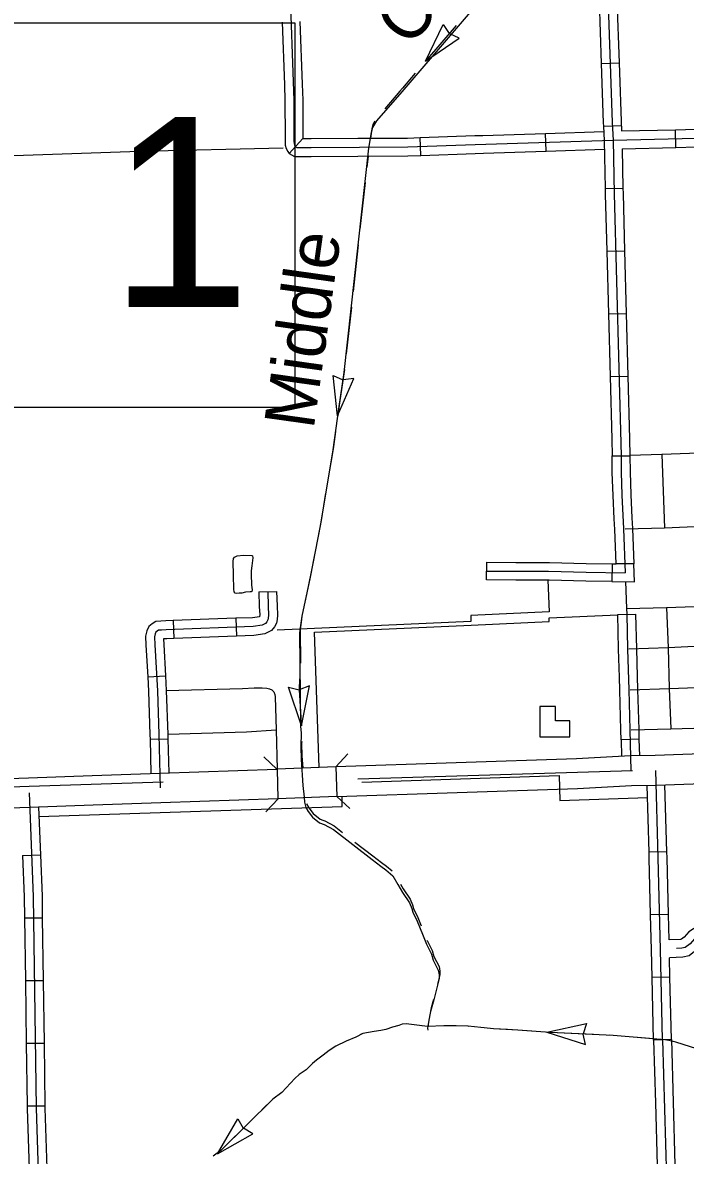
# Model space of a CAD drawing. Extents: x 1164457 to 1439835, y 1590918 to 1773502.
# Drawn here: x 1287953 to 1293538, y 1631604 to 1641151 of the extents above; entities that cross this region are included whole.
import ezdxf

# ---------------------------------------------------------------- set-up
doc = ezdxf.new("R2010")
doc.units = 0
for name, color, linetype in [('Level 15', 7, 'Continuous'), ('Level 31', 7, 'Continuous'), ('Level 32', 7, 'Continuous'), ('Level 33', 7, 'Continuous'), ('Level 34', 7, 'Continuous'), ('Level 35', 7, 'Continuous'), ('Level 37', 7, 'Continuous'), ('Level 43', 7, 'Continuous'), ('Level 45', 7, 'Continuous'), ('Level 5', 7, 'Continuous'), ('Level 58', 7, 'Continuous'), ('Level 6', 7, 'Continuous'), ('R_Draft', 7, 'Continuous')]:
    doc.layers.add(name, color=color, linetype=linetype)

msp = doc.modelspace()

# ---------------------------------------------------------------- linework, layer by layer
at = {"layer": 'Level 15'}
for points in [[(1294870.3, 1634777.6), (1294862.8, 1635027.5), (1294743.4, 1635023.9), (1294410.1, 1635010.5), (1294147.1, 1635001.7), (1293830.1, 1634993.2), (1293285.2, 1634972.7), (1293076, 1634969.7), (1292619.8, 1634946.4), (1290592.7, 1634878.6)], [(1287756.1, 1634777.3), (1288003.4, 1634785.6), (1288539.1, 1634805.7), (1289108.2, 1634825), (1290095.9, 1634859.3), (1290097.5, 1634859.4), (1290104.5, 1634609.5)], [(1290592.7, 1634878.6), (1290097.5, 1634859.4)], [(1290592.7, 1634878.6), (1290601, 1634628.8), (1292630.4, 1634696.6), (1293084.1, 1634719.8), (1293291.7, 1634722.8), (1293838.2, 1634743.4), (1294154.6, 1634751.8), (1294419.3, 1634760.7), (1294752.1, 1634774.1), (1294870.3, 1634777.6)], [(1290601, 1634628.8), (1290104.5, 1634609.5)], [(1290104.5, 1634609.5), (1289116.8, 1634575.2), (1288548, 1634555.9), (1288012.3, 1634535.7), (1287764.5, 1634527.4)]]:
    msp.add_lwpolyline(points, dxfattribs=at)
at = {"layer": 'Level 31'}
for p, q in [((1292921.8, 1637500.3), (1293071.8, 1637500.9)), ((1291863.4, 1636453.2), (1291864.6, 1636603.2)), ((1291864.6, 1636603.2), (1291864.6, 1636603.2)), ((1292920.8, 1636590.7), (1292919, 1636440.7)), ((1292969.8, 1636162.5), (1293119.7, 1636165.5)), ((1293147.6, 1635110.5), (1292997.6, 1635106.3)), ((1292997.6, 1635106.3), (1292997.6, 1635106.3))]:
    msp.add_line(p, q, dxfattribs=at)
for points in [[(1292938.9, 1636969.4), (1292929.6, 1637164.4), (1292922.4, 1637360.3), (1292921.8, 1637500.3)], [(1292996.8, 1637500.6), (1292997.4, 1637361.9), (1293004.5, 1637167.6), (1293018.1, 1636883.2), (1293032.2, 1636514.4)], [(1293071.8, 1637500.9), (1293072.4, 1637363.4), (1293079.4, 1637170.8), (1293088.7, 1636976.6)], [(1293104.4, 1636588.6), (1292954.2, 1636590.3), (1292943.2, 1636880), (1292938.9, 1636969.4)], [(1293088.7, 1636976.6), (1293093.1, 1636886.4), (1293104.4, 1636588.6)], [(1291864, 1636528.2), (1292109.3, 1636526.3), (1292386.3, 1636526.3), (1292701.3, 1636518.3), (1293032.2, 1636514.4)], [(1291864.6, 1636603.2), (1292109.6, 1636601.3), (1292387.2, 1636601.3), (1292393.9, 1636601.1)], [(1292393.9, 1636601.1), (1292702.7, 1636593.3), (1292920.8, 1636590.7)], [(1292919, 1636440.7), (1293110.1, 1636438.5), (1293104.4, 1636588.6)], [(1292920.8, 1636590.7), (1292954.2, 1636590.3)], [(1292390.1, 1636451.1), (1292385.3, 1636451.3), (1292109, 1636451.3), (1291863.4, 1636453.2)], [(1292919, 1636440.7), (1292699.9, 1636443.3), (1292390.1, 1636451.1)], [(1292982.9, 1635633.8), (1292975.6, 1635868.8), (1292969.8, 1636162.5)], [(1293044.7, 1636164), (1293050.6, 1635870.7), (1293061.3, 1635526.7), (1293070.3, 1635190.7), (1293080, 1634844.7)], [(1293119.7, 1636165.5), (1293125.6, 1635872.6), (1293132.9, 1635638.5)], [(1292997.6, 1635106.3), (1292995.3, 1635188.6), (1292986.3, 1635524.5), (1292982.9, 1635633.8)], [(1293132.9, 1635638.5), (1293136.3, 1635528.9), (1293145.3, 1635192.8), (1293147.6, 1635110.5)], [(1292997.6, 1635106.3), (1293001.6, 1634965.9)], [(1293147.6, 1635110.5), (1293151.5, 1634970.8)]]:
    msp.add_lwpolyline(points, dxfattribs=at)
at = {"layer": 'Level 32'}
for p, q in [((1292829.7, 1640806), (1292979.6, 1640811.1)), ((1292848.2, 1640276.9), (1292998, 1640284.7)), ((1293459, 1640098.8), (1293455.4, 1640248.7)), ((1292862.4, 1639751.6), (1293012.4, 1639754.6)), ((1292876.1, 1639223.3), (1293026.1, 1639227.2)), ((1292890.1, 1638695.5), (1293040, 1638699.4)), ((1292904.1, 1638167.7), (1293054, 1638171.6)), ((1289944.1, 1636352.4), (1290094.1, 1636356.7)), ((1289221.6, 1636110.5), (1289227.2, 1635960.6)), ((1289749.2, 1636130.3), (1289754.8, 1635980.4)), ((1289007.6, 1635636.9), (1289157.4, 1635645.3)), ((1289026.8, 1635111.6), (1289176.7, 1635115.5)), ((1293383.4, 1634163.1), (1293233.5, 1634158.7)), ((1287953.4, 1634130.1), (1288103.2, 1634136)), ((1287969.2, 1633604.3), (1288119.2, 1633606.3)), ((1293396.1, 1633634.8), (1293246.2, 1633631.3)), ((1293408.5, 1633106.9), (1293258.6, 1633103.4)), ((1287976.4, 1633076.4), (1288126.4, 1633078.4)), ((1287983.6, 1632548.4), (1288133.6, 1632550.4)), ((1293420.9, 1632579.1), (1293271, 1632575.6)), ((1287990.8, 1632020.5), (1288140.8, 1632022.5))]:
    msp.add_line(p, q, dxfattribs=at)
for points in [[(1292595.2, 1650835.6), (1292619.2, 1650245.4), (1292635.6, 1649303.5), (1292664.5, 1648188.9), (1292730.3, 1645988.2), (1292748.5, 1645496.5), (1292786.1, 1644344.5), (1292832.7, 1642827.7), (1292882.3, 1641465.2), (1292921.6, 1640309.2), (1292929.3, 1640161.1)], [(1292811.7, 1641333.7), (1292829.7, 1640806)], [(1292961.7, 1641338.8), (1292979.6, 1640811.1)], [(1292829.7, 1640806), (1292846.6, 1640306), (1292848.2, 1640276.9)], [(1292979.6, 1640811.1), (1292999.1, 1640237.8)], [(1292929.3, 1640161.1), (1293627.3, 1640177.8), (1294901.9, 1640225.9), (1295551.7, 1640247.8), (1297052.5, 1640298.3), (1297477.1, 1640311), (1298072.3, 1640333.4), (1298167.4, 1640347), (1298194.4, 1640359), (1298210.9, 1640377), (1298228.9, 1640389), (1298248.4, 1640392)], [(1292848.2, 1640276.9), (1292854.3, 1640158.4), (1292862.4, 1639751.6)], [(1292999.1, 1640237.8), (1293455.4, 1640248.7)], [(1293455.4, 1640248.7), (1293625, 1640252.8), (1293982, 1640266.3)], [(1292929.3, 1640161.1), (1292938.3, 1639707.6), (1292996.8, 1637500.6)], [(1293005.8, 1640087.9), (1293459, 1640098.8)], [(1293005.8, 1640087.9), (1293012.4, 1639754.6)], [(1293459, 1640098.8), (1293629.6, 1640102.9), (1293987.7, 1640116.4)], [(1292862.4, 1639751.6), (1292863.3, 1639705.9), (1292876.1, 1639223.3)], [(1293012.4, 1639754.6), (1293013.3, 1639709.4), (1293026.1, 1639227.2)], [(1292876.1, 1639223.3), (1292890.1, 1638695.5)], [(1293026.1, 1639227.2), (1293040, 1638699.4)], [(1292890.1, 1638695.5), (1292904.1, 1638167.7)], [(1293040, 1638699.4), (1293054, 1638171.6)], [(1292904.1, 1638167.7), (1292918, 1637639.8)], [(1293054, 1638171.6), (1293068, 1637643.8)], [(1292918, 1637639.8), (1292921.8, 1637500.3)], [(1293068, 1637643.8), (1293071.8, 1637500.9)], [(1290019.1, 1636354.5), (1290022.6, 1636232.5), (1290026.2, 1636157.8), (1290023.9, 1636132.6), (1290020.3, 1636116.4), (1290011.9, 1636100.2), (1290001.4, 1636086.8), (1289971.7, 1636071.4), (1289896, 1636060.8), (1289164.1, 1636033.3), (1289122.7, 1636030.9), (1289098.7, 1636029.2), (1289087.2, 1636022.7), (1289077.1, 1636014.4), (1289070.6, 1636000.1), (1289064.4, 1635973.5), (1289067.6, 1635906.6), (1289089.3, 1635519.8), (1289100.8, 1635149.8), (1289112.5, 1634700.1)], [(1289944.1, 1636352.4), (1289947.7, 1636229.6), (1289951, 1636159.4), (1289949.7, 1636144.5), (1289948.6, 1636143.9), (1289889.3, 1636135.6), (1289749.2, 1636130.3)], [(1290094.1, 1636356.7), (1290097.6, 1636235.3), (1290101.3, 1636156.2), (1290098.2, 1636121.1), (1290091.4, 1636090.6), (1290075.2, 1636059.4), (1290050.3, 1636027.7), (1289994.9, 1635998.9), (1289902.6, 1635986), (1289754.8, 1635980.4)], [(1289221.6, 1636110.5), (1289160.6, 1636108.2), (1289117.8, 1636105.8), (1289076.5, 1636102.7), (1289044.6, 1636084.7), (1289016.1, 1636061.3), (1288999.3, 1636024.5), (1288989, 1635980.3), (1288992.7, 1635902.7), (1289007.6, 1635636.9)], [(1289749.2, 1636130.3), (1289221.6, 1636110.5)], [(1289227.2, 1635960.6), (1289167.7, 1635958.4), (1289140.3, 1635956.8), (1289142.5, 1635910.5), (1289157.4, 1635645.3)], [(1289754.8, 1635980.4), (1289227.2, 1635960.6)], [(1289007.6, 1635636.9), (1289014.3, 1635516.5), (1289025.8, 1635147.7), (1289026.8, 1635111.6)], [(1289157.4, 1635645.3), (1289164.2, 1635523.1), (1289175.8, 1635152), (1289176.7, 1635115.5)], [(1289026.8, 1635111.6), (1289034.3, 1634822.5)], [(1289176.7, 1635115.5), (1289184.2, 1634827.6)], [(1293345.9, 1632577.3), (1293328, 1633338.7), (1293309.9, 1634110.7), (1293288.5, 1634847.7)], [(1293233.5, 1634158.7), (1293217.1, 1634721.7)], [(1293383.4, 1634163.1), (1293367, 1634725.6)], [(1288007.8, 1634660.6), (1288041.8, 1633785.8), (1288066.1, 1632000.6), (1288103.1, 1630845.4)], [(1288087.6, 1634538.6), (1288103.2, 1634136)], [(1293246.2, 1633631.3), (1293234.9, 1634108.7), (1293233.5, 1634158.7)], [(1293396.1, 1633634.8), (1293384.9, 1634112.7), (1293383.4, 1634163.1)], [(1287953.4, 1634130.1), (1287966.8, 1633783.9), (1287969.2, 1633604.3)], [(1288103.2, 1634136), (1288116.8, 1633787.8), (1288119.2, 1633606.3)], [(1294219.2, 1633888.6), (1294219.6, 1633848.5), (1294217.5, 1633803.8), (1294200.4, 1633746.2), (1294172.7, 1633671.6), (1294138.6, 1633584.1), (1294110.9, 1633543.6), (1294083.2, 1633511.6), (1294057.6, 1633496.7), (1294023.5, 1633490.3), (1293808.2, 1633492.4), (1293752.8, 1633488.2), (1293720.8, 1633481.8), (1293678.2, 1633469), (1293616.3, 1633428.5), (1293578, 1633387.9), (1293537.5, 1633356), (1293507.6, 1633349.6), (1293465, 1633347.4)], [(1287969.2, 1633604.3), (1287976.4, 1633076.4)], [(1288119.2, 1633606.3), (1288126.4, 1633078.4)], [(1293258.6, 1633103.4), (1293253.1, 1633337), (1293246.2, 1633631.3)], [(1293401.2, 1633419.3), (1293396.1, 1633634.8)], [(1293917.1, 1633566.4), (1293805.7, 1633567.5), (1293742.5, 1633562.6), (1293702.6, 1633554.6), (1293646.2, 1633537.7), (1293567.9, 1633486.4), (1293527.2, 1633443.4), (1293504.7, 1633425.6), (1293497.8, 1633424.2), (1293401.2, 1633419.3)], [(1293915.6, 1633416.4), (1293810.7, 1633417.4), (1293763, 1633413.7), (1293739, 1633408.9), (1293710.2, 1633400.3), (1293664.8, 1633370.5), (1293628.7, 1633332.4), (1293570.3, 1633286.3), (1293517.4, 1633275), (1293404.7, 1633269.3)], [(1293408.5, 1633106.9), (1293404.7, 1633269.3)], [(1293271, 1632575.2), (1293258.6, 1633103.4)], [(1293420.9, 1632579.5), (1293408.5, 1633106.9)], [(1287976.4, 1633076.4), (1287983.6, 1632548.4)], [(1288126.4, 1633078.4), (1288133.6, 1632550.4)], [(1287983.6, 1632548.4), (1287990.8, 1632020.5)], [(1288133.6, 1632550.4), (1288140.8, 1632022.5)], [(1287990.8, 1632020.5), (1287991.1, 1631998.9), (1288007.3, 1631491.3)], [(1288140.8, 1632022.5), (1288141, 1632002.3), (1288157.3, 1631496.1)]]:
    msp.add_lwpolyline(points, dxfattribs=at)
at = {"layer": 'Level 33'}
for points in [[(1293339.9, 1637512), (1293363.7, 1636894.1)], [(1293032.5, 1636883.6), (1293363.7, 1636894.1), (1293744.9, 1636909.2), (1293984.9, 1636923.4), (1294334.7, 1636935.3)], [(1293035, 1636439.4), (1293043.7, 1636211.9), (1293044.7, 1636164)], [(1293043.7, 1636211.9), (1293378.6, 1636221.7), (1293770.5, 1636236.2), (1294359.8, 1636251.3)], [(1293378.6, 1636221.7), (1293393.2, 1635882.7), (1293402.6, 1635539.2), (1293415.2, 1635198.2)], [(1294371.8, 1635912.7), (1293933.8, 1635901.1), (1293781.6, 1635902.2), (1293393.2, 1635882.7), (1293062.1, 1635871.1)], [(1293402.6, 1635539.2), (1293790, 1635553.7), (1294385.3, 1635577.4)], [(1293081.9, 1635191), (1293415.2, 1635198.2), (1293705.5, 1635207.1), (1293814.4, 1635211.7), (1293829.4, 1635211.7)]]:
    msp.add_lwpolyline(points, dxfattribs=at)
at = {"layer": 'Level 34'}
for points in [[(1295681.5, 1637580.2), (1295410.1, 1637568.9), (1294654.4, 1637551), (1294315, 1637541.9), (1293960.9, 1637532.7), (1293339.9, 1637512), (1293071.7, 1637503.1)], [(1289164.2, 1635522.3), (1289805.4, 1635539.8), (1289903.7, 1635543.4), (1289972, 1635544.1), (1290011.4, 1635541), (1290033.6, 1635535.2), (1290052.6, 1635526.4), (1290069.1, 1635511), (1290078, 1635489), (1290081.3, 1635468.8), (1290089.6, 1635190.4), (1290097.5, 1634859.4)], [(1293072.1, 1635527.1), (1293402.6, 1635539.2)], [(1289175.7, 1635154.1), (1289840.9, 1635173.9), (1290089.6, 1635190.4)]]:
    msp.add_lwpolyline(points, dxfattribs=at)
at = {"layer": 'Level 35'}
for points in [[(1289729.6, 1636493.1), (1289728.4, 1636608), (1289729.6, 1636634.1), (1289737.9, 1636645.9), (1289761.6, 1636655.4), (1289813.7, 1636661.3), (1289883.5, 1636660.2), (1289890.6, 1636656.6), (1289893, 1636640), (1289883.5, 1636571.3), (1289878.8, 1636531), (1289880, 1636501.4)], [(1289880, 1636501.4), (1289882.3, 1636409), (1289887.1, 1636368.8), (1289885.9, 1636356.9), (1289880, 1636353.4), (1289870.5, 1636352.2), (1289832.6, 1636351), (1289799.5, 1636342.7), (1289778.1, 1636341.5), (1289759.2, 1636340.3), (1289743.8, 1636342.7), (1289736.7, 1636352.2), (1289734.3, 1636377), (1289729.6, 1636493.1)]]:
    msp.add_lwpolyline(points, dxfattribs=at)
at = {"layer": 'Level 37'}
for points in [[(1289986.6, 1634961.5), (1290096.5, 1634859.4)], [(1290592.3, 1634878.6), (1290694.4, 1634988.5)], [(1290711.3, 1634526.6), (1290601.4, 1634628.8)], [(1290105.6, 1634609.5), (1290003.4, 1634499.7)]]:
    msp.add_lwpolyline(points, dxfattribs=at)
at = {"layer": 'Level 43'}
for p, q in [((1291348.3, 1640824.9), (1291496.5, 1641134.5)), ((1291496.5, 1641134.5), (1291548.1, 1641059.1)), ((1291348.3, 1640824.9), (1291631.4, 1641018.9)), ((1291631.4, 1641018.9), (1291549, 1641058.3)), ((1290607.9, 1637836.1), (1290569, 1638177.1)), ((1290569, 1638177.1), (1290652.8, 1638140.7)), ((1290607.9, 1637836.1), (1290744.7, 1638150.9)), ((1290744.7, 1638150.9), (1290654, 1638140.5)), ((1290194, 1635549.5), (1290282.7, 1635527.8)), ((1290304, 1635224.5), (1290194, 1635549.5)), ((1290371.2, 1635561), (1290282.7, 1635527.8)), ((1290304, 1635224.5), (1290371.2, 1635561)), ((1292369.8, 1632641.6), (1292705.2, 1632714.2)), ((1292705.2, 1632714.2), (1292677.4, 1632627.2)), ((1292369.8, 1632641.6), (1292696.6, 1632536.8)), ((1292696.6, 1632536.8), (1292677.3, 1632626)), ((1289594.3, 1631615.9), (1289768.1, 1631911.9)), ((1289768.1, 1631911.9), (1289813.2, 1631832.4)), ((1289594.3, 1631615.9), (1289892.8, 1631785.3)), ((1289892.8, 1631785.3), (1289814.1, 1631831.5))]:
    msp.add_line(p, q, dxfattribs=at)
for points in [[(1292471.3, 1642111.9), (1291148, 1640567.2), (1290936.9, 1640321.8), (1290919.2, 1640294.8), (1290902.7, 1640267), (1290891.3, 1640224.3), (1290869.2, 1640093.5), (1290661.4, 1638202), (1290618.8, 1637916.7), (1290567.4, 1637548.9), (1290463.1, 1636924.1), (1290376.4, 1636478.2), (1290306.5, 1636147.6), (1290294.7, 1636068.3), (1290285.8, 1636006.7), (1290296.2, 1635219.6), (1290300.8, 1635163.6), (1290299.1, 1635048.6), (1290301.4, 1634939.6), (1290315.5, 1634721.8), (1290325, 1634622.3), (1290328.1, 1634581.8), (1290340.8, 1634535.3), (1290359.7, 1634502.1), (1290395.6, 1634455.1), (1290456, 1634407.7), (1290495, 1634392.3), (1290572.6, 1634349.3), (1290899.3, 1634096.3), (1290971.5, 1634042.5), (1291015.3, 1634010.5), (1291074.2, 1633959), (1291115.4, 1633887), (1291154, 1633820.1), (1291213.6, 1633732.7), (1291233.3, 1633683.6), (1291241.6, 1633654.8), (1291277, 1633578.3), (1291324.2, 1633467.7), (1291355.9, 1633383.6), (1291398.8, 1633298.7), (1291412.9, 1633249), (1291456.6, 1633164.9), (1291463.7, 1633125.5), (1291464.9, 1633093.5), (1291437.8, 1632994.4), (1291418.1, 1632914.4), (1291389.8, 1632815.8), (1291375.2, 1632742.9), (1291364.9, 1632677), (1291367.3, 1632659.3)], [(1291605.9, 1641125.7), (1291348.3, 1640824.9)], [(1291262.4, 1640724.7), (1291153.7, 1640597.8), (1291133.5, 1640574.4)], [(1291133.5, 1640574.4), (1291004.4, 1640424.2)], [(1290922.3, 1640321.2), (1290908.4, 1640297.6), (1290896.9, 1640254.9), (1290883.7, 1640176.6)], [(1290864.1, 1640026.4), (1290853.9, 1639933.5)], [(1290839.5, 1639802.3), (1290796.2, 1639408.7)], [(1290781.8, 1639277.5), (1290738.6, 1638883.8)], [(1290724.2, 1638752.6), (1290680.9, 1638359)], [(1290666.3, 1638227.8), (1290624.5, 1637947.3), (1290608.9, 1637836)], [(1290590.7, 1637705.2), (1290573.1, 1637579.5), (1290561.4, 1637509.4)], [(1290561.4, 1637509.4), (1290528.8, 1637314.1)], [(1290507, 1637184), (1290468.7, 1636954.6), (1290437.5, 1636794.1)], [(1290412.3, 1636664.6), (1290382.1, 1636508.7), (1290333, 1636276.6)], [(1290307.6, 1636147.1), (1290300.4, 1636098.9), (1290291.5, 1636037.3), (1290295.2, 1635752.3)], [(1290286.9, 1635620.6), (1290282.7, 1635527.8), (1290301.8, 1635250.2), (1290304, 1635224.5)], [(1290304.9, 1635092.6), (1290304.7, 1635079.1), (1290307.1, 1634970.2), (1290313.7, 1634867.8)], [(1290346, 1634567.3), (1290346.4, 1634565.9), (1290365.4, 1634532.7), (1290401.2, 1634485.6), (1290461.6, 1634438.3), (1290482.5, 1634430)], [(1290482.5, 1634430), (1290500.7, 1634422.9), (1290578.3, 1634379.9), (1290649.2, 1634324.9)], [(1290753.6, 1634244.1), (1290905, 1634126.9), (1290977.1, 1634073.1), (1291020.9, 1634041.1), (1291066.3, 1634001.5)], [(1291136.6, 1633890.7), (1291159.6, 1633850.7), (1291219.2, 1633763.3), (1291239, 1633714.2), (1291247.3, 1633685.3), (1291282.7, 1633608.9), (1291312.8, 1633538.2)], [(1291361.1, 1633415.4), (1291361.6, 1633414.2), (1291404.4, 1633329.3), (1291418.6, 1633279.5), (1291462.3, 1633195.5), (1291469.4, 1633156.1), (1291470.6, 1633124.1), (1291449.2, 1633045.9)], [(1291416, 1632918.1), (1291395.4, 1632846.4), (1291380.9, 1632773.5), (1291370.6, 1632707.6), (1291373, 1632689.9)], [(1293697.1, 1632481), (1293458.8, 1632558.5), (1293398.9, 1632571.6), (1293364.6, 1632577.9), (1292930, 1632614.4), (1292400, 1632640.1), (1292127.9, 1632659.1), (1291921.1, 1632670.1), (1291707.8, 1632691.2), (1291607.5, 1632695.4), (1291504.3, 1632695), (1291366.3, 1632689.6), (1291186.2, 1632711), (1291151.4, 1632709.2), (1291122.8, 1632699.1), (1291071.4, 1632684.6), (1291014, 1632665.4), (1290971.4, 1632654.7), (1290916.9, 1632646.4), (1290819.8, 1632631), (1290760.6, 1632599.9), (1290681.1, 1632566), (1290592.1, 1632523.5), (1290537.8, 1632486.7), (1290485.6, 1632447.1), (1290430.5, 1632405.2), (1290395.8, 1632377.4), (1290343.2, 1632325.7), (1290283.1, 1632284.5), (1290248.1, 1632252.8), (1290138.1, 1632132.7), (1290063, 1632077.7), (1289622.9, 1631644.1), (1289557.9, 1631597.4)], [(1291185.3, 1632711), (1291151.4, 1632709.2), (1291122.8, 1632699.1), (1291071.4, 1632684.6), (1291014, 1632665.4), (1290971.4, 1632654.7), (1290916.9, 1632646.4), (1290819.8, 1632631), (1290801.7, 1632621.5)], [(1291711.8, 1632690.8), (1291707.8, 1632691.2), (1291607.5, 1632695.4), (1291504.3, 1632695), (1291366.3, 1632689.6), (1291316.3, 1632695.5)], [(1292040.6, 1632663.7), (1291921.1, 1632670.1), (1291843.1, 1632677.8)], [(1292238.2, 1632651.4), (1292127.9, 1632659.1), (1292040.6, 1632663.7)], [(1292765.4, 1632622.4), (1292400, 1632640.1), (1292369.9, 1632642.2)], [(1293270.7, 1632585.8), (1292930, 1632614.4), (1292897.2, 1632616)], [(1290681.9, 1632566.3), (1290681.1, 1632566), (1290592.1, 1632523.5), (1290537.8, 1632486.7), (1290485.6, 1632447.1), (1290430.5, 1632405.2), (1290395.8, 1632377.4), (1290358.9, 1632341.1)], [(1293799, 1632444.4), (1293697.1, 1632481), (1293458.8, 1632558.5), (1293422.5, 1632566.4)], [(1290255.6, 1632259.6), (1290248.1, 1632252.8), (1290138.1, 1632132.7), (1290063, 1632077.7), (1289970.4, 1631986.5)], [(1289876.4, 1631893.8), (1289622.9, 1631644.1), (1289590.3, 1631620.7)]]:
    msp.add_lwpolyline(points, dxfattribs=at)
at = {"layer": 'Level 45'}
for p, q in [((1290198.9, 1640046.8), (1290314.7, 1640172.9)), ((1291309.2, 1640032.2), (1291303.8, 1640182.1)), ((1292364.3, 1640067.8), (1292359.5, 1640217.8))]:
    msp.add_line(p, q, dxfattribs=at)
for points in [[(1292803.2, 1642801.9), (1290299.1, 1642808.5), (1290275.8, 1642804.1), (1290255, 1642795.7), (1290243.4, 1642787.9), (1290218.1, 1642768.9), (1290198.3, 1642747.4), (1290182.2, 1642725.7), (1290172.5, 1642696.8), (1290166.1, 1642652.6), (1290165.1, 1642553.1), (1290238.8, 1640495.6), (1290239.7, 1640188), (1290239.7, 1640151.2), (1290240.6, 1640130), (1290243.3, 1640119.2), (1290252.5, 1640103.5), (1290263.6, 1640097.8), (1290281.9, 1640097.9), (1290308.7, 1640097.8), (1290385.1, 1640098.7), (1291198.8, 1640103.3), (1291765.8, 1640123.6), (1292929.3, 1640161.1)], [(1290140.2, 1641154.1), (1290159, 1640626.4)], [(1290290.1, 1641159.5), (1290308.9, 1640631.8)], [(1290308.9, 1640631.8), (1290313.8, 1640497), (1290314.7, 1640172.9)], [(1290159, 1640626.4), (1290163.8, 1640494.1), (1290164.7, 1640187.9), (1290164.7, 1640149.6), (1290166, 1640119.2), (1290173.2, 1640090.5), (1290187.6, 1640066)], [(1290314.7, 1640172.9), (1290384.5, 1640173.7), (1290778.2, 1640176)], [(1290778.2, 1640176), (1291197.2, 1640178.3), (1291303.8, 1640182.1)], [(1291303.8, 1640182.1), (1291763.2, 1640198.6), (1291831.8, 1640200.8)], [(1291831.8, 1640200.8), (1292359.5, 1640217.8)], [(1292359.5, 1640217.8), (1292850.4, 1640233.6)], [(1290187.6, 1640065.9), (1290198.9, 1640046.8), (1290245.6, 1640022.8), (1290281.9, 1640022.9), (1290309.1, 1640022.8), (1290385.8, 1640023.7), (1290779, 1640026)], [(1291836.6, 1640050.8), (1292364.3, 1640067.8)], [(1292364.3, 1640067.8), (1292855.8, 1640083.7)], [(1290779, 1640026), (1291200.3, 1640028.3), (1291309.2, 1640032.2)], [(1291309.2, 1640032.2), (1291768.3, 1640048.6), (1291836.6, 1640050.8)], [(1293271, 1632575.6), (1293286, 1632047.4)], [(1293345.9, 1632577.3), (1293395.8, 1630824.2)], [(1293420.9, 1632579.1), (1293435.9, 1632051.7)], [(1293286, 1632047.4), (1293301, 1631519.6)], [(1293435.9, 1632051.7), (1293450.9, 1631523.9)]]:
    msp.add_lwpolyline(points, dxfattribs=at)
at = {"layer": 'Level 5'}
msp.add_lwpolyline([(1287712.4, 1640026.5), (1288939.5, 1640067.5), (1290150.1, 1640095.7)], dxfattribs=at)
at = {"layer": 'Level 58'}
msp.add_lwpolyline([(1292311.1, 1635132.2), (1292565.1, 1635132.2), (1292565.1, 1635266.2), (1292444.9, 1635266.2), (1292444.9, 1635386.2), (1292311.1, 1635386.2)], close=True, dxfattribs=at)
at = {"layer": 'Level 6'}
for points in [[(1292380.3, 1636451.3), (1292389.4, 1636184), (1291730, 1636153.8), (1291731.7, 1636103.8), (1290413, 1636043.4), (1290098.1, 1636028.9)], [(1290452.9, 1634873.2), (1290414.4, 1636013.4), (1291732.8, 1636073.8), (1292392.1, 1636104), (1292391.1, 1636134), (1292969.8, 1636160.6)], [(1293092, 1634844.9), (1290777.1, 1634775.2)], [(1289136.3, 1634748.5), (1288007.7, 1634712.6), (1287771.5, 1634705)], [(1290813.2, 1634750.5), (1292474.3, 1634805.7)], [(1292474.3, 1634805.7), (1292479.3, 1634595.7), (1293220, 1634620.3)], [(1288090.7, 1634460), (1290647.2, 1634544.9), (1290644.9, 1634630.2)]]:
    msp.add_lwpolyline(points, dxfattribs=at)
at = {"layer": 'R_Draft'}
msp.add_lwpolyline([(1287096.8, 1637909.7), (1290251.3, 1637909.7), (1290251.3, 1641147.1), (1287096.8, 1641147.1)], close=True, dxfattribs=at)

# ---------------------------------------------------------------- texts
at = {"layer": 'Level 43'}
for s, rotation, p in [('Creek', 49.81626, (1291210.4, 1640930.1)), ('Middle', 82.00271, (1290405.1, 1637715.3))]:
    msp.add_text(s, height=422, rotation=rotation, dxfattribs=at).set_placement(p)
at = {"layer": 'R_Draft'}
msp.add_text('1', height=1600, dxfattribs=at).set_placement((1288685, 1638755.3))

doc.saveas('drawing.dxf')
